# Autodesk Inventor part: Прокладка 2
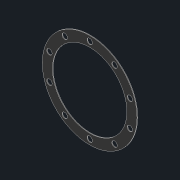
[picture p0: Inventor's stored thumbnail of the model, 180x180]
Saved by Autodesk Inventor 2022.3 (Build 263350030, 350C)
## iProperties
Created: 2022-08
Part Number: Прокладка 2
Material: Резина
Document SubType Name: Modeling
Designer: Карташов
Density: 0.93 g/cm^3
Appearance: Резина — черная
Author: Карташов
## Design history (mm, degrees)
sketch "Эскиз1"
  geometry: L1 (320, 7.5)-(320, -7.5) reference; L2 (320, 7.5)-(226.741, 7.5) reference; L3 (168, 77.353)-(168, 82.5) reference; L4 (158, 82.5)-(168, 82.5) reference; L5 (158, 82.5)-(158, 80.25) reference; L6 (118, 80.25)-(118, 82.5) reference; L7 (108, 82.5)-(118, 82.5) reference; L8 (108, 82.5)-(108, 77.353) reference; L9 (49.259, 7.5)-(28.374, 7.5) reference; L10 (-10, 55.746)-(-10, 77.5) reference; L11 (-20, 77.5)-(-10, 77.5) reference; L12 (-20, 77.5)-(-20, 59.582) reference; L13 (-60, 59.582)-(-60, 77.5) reference; L14 (-70, 77.5)-(-60, 77.5) reference; L15 (-70, 77.5)-(-70, 55.746) reference; L16 (-108.374, 7.5)-(-131.905, 7.5) reference; L17 (-185, 52.291)-(-185, 78.5) reference; L18 (-195, 78.5)-(-185, 78.5) reference; L19 (-195, 78.5)-(-195, 52.291) reference; L20 (-248.095, 7.5)-(-320, 7.5) reference; L21 (-320, -7.5)-(-320, 7.5) reference; L22 (-320, -7.5)-(-235, -7.5) reference; L23 (-145, -7.5)-(-95, -7.5) reference; L24 (15, -7.5)-(63, -7.5) reference; L25 (213, -7.5)-(320, -7.5) reference; L26 (285, -187.5)-(285, -22.5) reference; L27 (285, -187.5)-(300, -187.5) reference; L28 (300, -187.5)-(300, -22.5) reference; L29 (300, -22.5)-(320, -22.5) reference; L30 (320, -22.5)-(320, -7.5) reference; L31 (320, -7.5)-(213, -7.5) reference; L32 (63, -7.5)-(15, -7.5) reference; L33 (-95, -7.5)-(-145, -7.5) reference; L34 (-235, -7.5)-(-320, -7.5) reference; L35 (-320, -7.5)-(-320, -22.5) reference; L36 (-320, -22.5)-(-305, -22.5) reference; L37 (-300, -27.5)-(-300, -187.5) reference; L38 (-300, -187.5)-(-285, -187.5) reference; L39 (-285, -27.5)-(-285, -187.5) reference; L40 (-248.095, -22.5)-(-280, -22.5) reference; L41 (-155, -56.234)-(-154.394, -56.234) reference; L42 (-108.374, -22.5)-(-131.905, -22.5) reference; L43 (49.259, -22.5)-(28.374, -22.5) reference; L44 (285, -22.5)-(226.741, -22.5) reference; C1 r 4 at (138, 75) reference; C2 r 4 at (-3.263, 43.064) reference; C3 r 4 at (-144.534, 18.75) reference; C4 r 4 at (-235.466, 18.75) reference; C5 r 4 at (-40, 55) reference; C6 r 4 at (89.508, 59.244) reference; C7 r 4 at (186.492, 59.244) reference; C8 r 4 at (19.441, 11.814) reference; C9 r 4 at (-99.441, 11.814) reference; C10 r 4 at (-190, 45) reference; C11 r 4 at (-76.737, 43.064) reference; C12 r 4 at (59.538, 17.994) reference; C13 r 4 at (216.462, 17.994) reference; C14 r 4 at (186.492, -74.244) reference; C15 r 4 at (216.462, -32.994) reference; C16 r 4 at (59.538, -32.994) reference; C17 r 4 at (89.508, -74.244) reference; C18 r 4 at (138, -90) reference; C19 r 4 at (-3.263, -58.064) reference; C20 r 4 at (19.441, -26.814) reference; C21 r 4 at (-99.441, -26.814) reference; C22 r 4 at (-76.737, -58.064) reference; C23 r 4 at (-40, -70) reference; C24 r 4 at (-190, -60) reference; C25 r 4 at (-144.534, -33.75) reference; C26 r 4 at (-235.466, -33.75) reference; C27 r 70 at (-40, -7.5); A1 r 90 centre (138, -7.5) between (226.741, 7.5) and (168, 77.353) reference; A2 r 90 centre (138, -7.5) between (158, 80.25) and (118, 80.25) reference; A3 r 90 centre (138, -7.5) between (108, 77.353) and (49.259, 7.5) reference; A4 r 70 centre (-40, -7.5) between (28.374, 7.5) and (-10, 55.746) reference; A5 r 70 centre (-40, -7.5) between (-20, 59.582) and (-60, 59.582) reference; A6 r 70 centre (-40, -7.5) between (-70, 55.746) and (-108.374, 7.5) reference; A7 r 60 centre (-190, -7.5) between (-131.905, 7.5) and (-185, 52.291) reference; A8 r 60 centre (-190, -7.5) between (-195, 52.291) and (-248.095, 7.5) reference; A9 r 45 centre (-190, -7.5) between (-145, -7.5) and (-235, -7.5) reference; A10 r 55 centre (-40, -7.5) between (15, -7.5) and (-95, -7.5) reference; A11 r 75 centre (138, -7.5) between (213, -7.5) and (63, -7.5) reference; A12 r 75 centre (138, -7.5) between (63, -7.5) and (213, -7.5) reference; A13 r 55 centre (-40, -7.5) between (-95, -7.5) and (15, -7.5) reference; A14 r 45 centre (-190, -7.5) between (-235, -7.5) and (-145, -7.5) reference; A15 r 5 centre (-305, -27.5) between (-300, -27.5) and (-305, -22.5) reference; A16 r 5 centre (-280, -27.5) between (-280, -22.5) and (-285, -27.5) reference; A17 r 60 centre (-190, -7.5) between (-248.095, -22.5) and (-225, -56.234) reference; A18 r 60 centre (-190, -7.5) between (-225, -56.234) and (-215, -62.044) reference; A19 r 60 centre (-190, -7.5) between (-215, -62.044) and (-165, -62.044) reference; A20 r 60 centre (-190, -7.5) between (-165, -62.044) and (-155, -56.234) reference; A21 r 4.5 centre (-150.5, -58.49) between (-153.256, -54.933) and (-154.394, -56.234) reference; A22 r 60 centre (-190, -7.5) between (-153.256, -54.933) and (-131.905, -22.5) reference; A23 r 70 centre (-40, -7.5) between (-108.374, -22.5) and (-75, -68.122) reference; A24 r 70 centre (-40, -7.5) between (-75, -68.122) and (-65, -72.883) reference; A25 r 70 centre (-40, -7.5) between (-65, -72.883) and (-15, -72.883) reference; A26 r 70 centre (-40, -7.5) between (-15, -72.883) and (-5, -68.122) reference; A27 r 70 centre (-40, -7.5) between (-5, -68.122) and (28.374, -22.5) reference; A28 r 90 centre (138, -7.5) between (49.259, -22.5) and (103, -90.416) reference; A29 r 90 centre (138, -7.5) between (103, -90.416) and (113, -93.958) reference; A30 r 90 centre (138, -7.5) between (113, -93.958) and (163, -93.958) reference; A31 r 90 centre (138, -7.5) between (163, -93.958) and (173, -90.416) reference; A32 r 90 centre (138, -7.5) between (173, -90.416) and (226.741, -22.5) reference; 9 further points
  constraints: 1 centre point, 1 coincident, 1 concentric
extrude "Выдавливание1" new body sketch "Эскиз1" distance "d0" = 1; taper "d1" = 0 deg
node "Твердое тело1"
node "Ссылка1"
node "Ссылка2"
